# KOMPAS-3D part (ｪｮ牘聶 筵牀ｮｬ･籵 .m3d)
File: created 24.09.2017 21:29:05, last saved 08.10.2017 22:58:18.
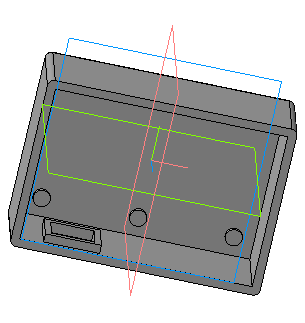
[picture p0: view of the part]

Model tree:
1. Эскиз:4
2. Операция выдавливания:3
     Толщина стенки 1 = 2; Расстояние 1 = 20
3. Эскиз:5
4. Операция выдавливания:4
     Расстояние 1 = 25; Расстояние 2 = 2
5. Эскиз:7
6. Операция выдавливания:6
     Расстояние 1 = 1; Угол 1 = 1; Расстояние 2 = 11
7. Скругление:1
     Радиус = 1.5
8. Эскиз:8
9. Вырезать элемент выдавливания:1
     Расстояние 2 = 2; Расстояние 1 = 10
10. Скругление:2
     Радиус = 1.5
11. Эскиз:9
12. Операция выдавливания:7
     Расстояние 1 = 2; Расстояние 2 = 2
13. Эскиз:10  (labels: ā␣0)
